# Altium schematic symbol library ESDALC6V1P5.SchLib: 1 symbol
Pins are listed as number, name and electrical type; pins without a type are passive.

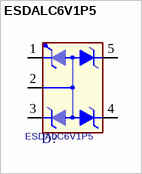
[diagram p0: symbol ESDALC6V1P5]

## ESDALC6V1P5
designator D?
footprint ST_SOT665
pins: 1, 2, 3, 4, 5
